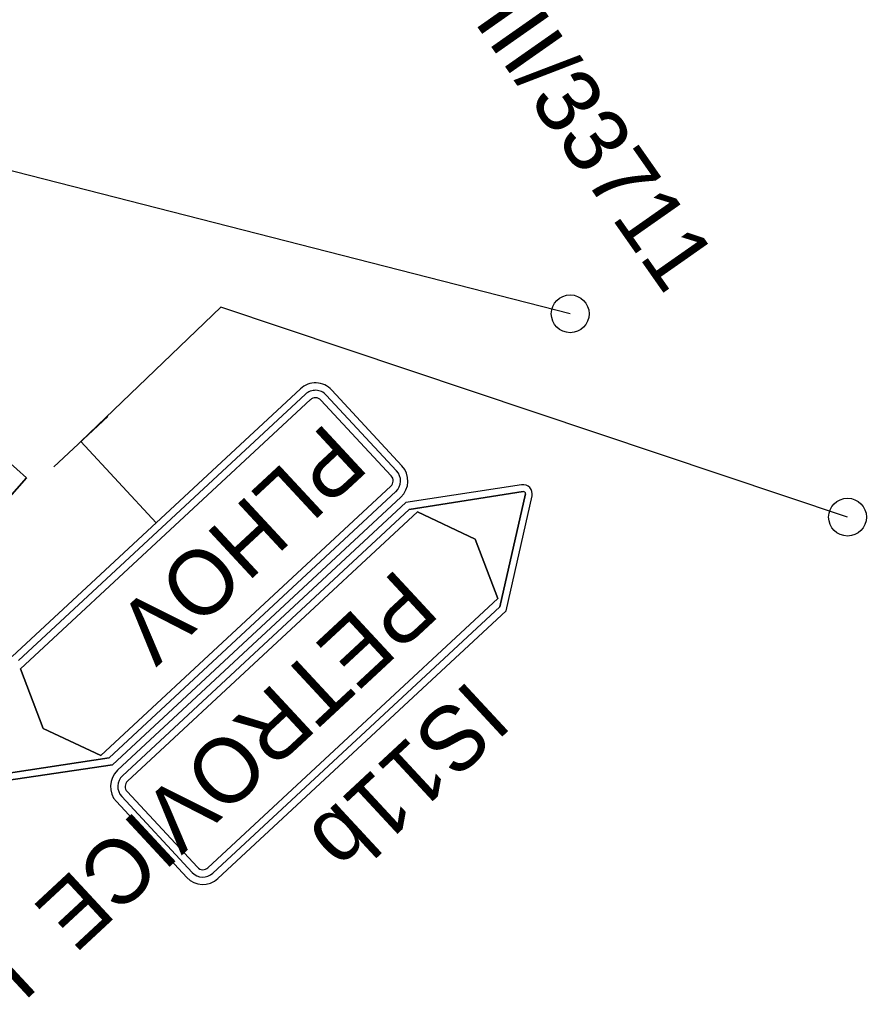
# Model space of a CAD drawing. Extents: x -688893 to -679983, y -1088371 to -1075771.
# Drawn here: x -684623 to -683934, y -1077302 to -1076507 of the extents above; entities that cross this region are included whole.
import ezdxf

# ---------------------------------------------------------------- set-up
doc = ezdxf.new("R2010")
doc.units = 0
for name, color, linetype in [('S popis', 7, 'Continuous'), ('SDZ', 7, 'Continuous'), ('SDZ ozn', 7, 'Continuous'), ('SDZ plochy', 7, 'Continuous'), ('SDZ symbol', 7, 'Continuous')]:
    doc.layers.add(name, color=color, linetype=linetype)

msp = doc.modelspace()

# ---------------------------------------------------------------- linework, layer by layer
at = {"layer": 'SDZ'}
for p, q in [((-684954.23, -1076581.35), (-684617.13, -1076879.46)), ((-684628.89, -1077024.86), (-684394.53, -1076807.26)), ((-684390.45, -1076811.66), (-684623.49, -1077028.03)), ((-684316.34, -1076873.84), (-684373.49, -1076812.28)), ((-684369.09, -1076808.2), (-684311.94, -1076869.76)), ((-684622.04, -1077034.88), (-684386.37, -1076816.05)), ((-684377.89, -1076816.37), (-684320.73, -1076877.92)), ((-684550.96, -1076829.69), (-684594.93, -1076870.52)), ((-684511.71, -1076916.06), (-684572.95, -1076850.11)), ((-684617.13, -1076879.46), (-684815.87, -1077104.19)), ((-684214.7, -1076885.22), (-684308.8, -1076899.59)), ((-684321.05, -1076886.4), (-684556.72, -1077105.23)), ((-684550, -1077107.18), (-684316.96, -1076890.8)), ((-684306.04, -1076905.22), (-684213.35, -1076890.73)), ((-684211.65, -1076892.55), (-684232.55, -1076984.36)), ((-684312.88, -1076895.2), (-684547.24, -1077112.8)), ((-684308.8, -1076899.59), (-684543.15, -1077117.19)), ((-684227.15, -1076987.53), (-684206.25, -1076894.27)), ((-684206.29, -1076894.48), (-684206.29, -1076894.48)), ((-684539.07, -1077121.59), (-684306.04, -1076905.22)), ((-684299.31, -1076907.16), (-684534.99, -1077125.99)), ((-684252.58, -1076929.27), (-684299.31, -1076907.16)), ((-684233.99, -1076977.51), (-684252.58, -1076929.27)), ((-684469.67, -1077196.34), (-684233.99, -1076977.51)), ((-684232.55, -1076984.36), (-684465.58, -1077200.74)), ((-684461.5, -1077205.13), (-684227.15, -1076987.53)), ((-684603.45, -1077083.12), (-684622.04, -1077034.88)), ((-684556.72, -1077105.23), (-684603.45, -1077083.12)), ((-684643.11, -1077121.22), (-684550, -1077107.18)), ((-684547.24, -1077112.8), (-684641.79, -1077126.74)), ((-684482.54, -1077200.11), (-684539.7, -1077138.55)), ((-684535.3, -1077134.47), (-684478.15, -1077196.02)), ((-684544.1, -1077142.63), (-684486.94, -1077204.19))]:
    msp.add_line(p, q, dxfattribs=at)
for points in [[(-684175.23, -1076746.27), (-685042.81, -1076524.62), (-685121.02, -1076634.1)], [(-683949.83, -1076911.5), (-684459.24, -1076740.97), (-684572.95, -1076850.11)]]:
    msp.add_lwpolyline(points, dxfattribs=at)
for centre in [(-684175.23, -1076746.27), (-683949.83, -1076911.5)]:
    msp.add_circle(centre, 15.36, dxfattribs=at)
for centre, radius, start, end in [((-684382.28, -1076820.45), 18, 42.87701, 132.87701), ((-684382.28, -1076820.45), 12, 42.87701, 132.87701), ((-684382.28, -1076820.45), 6, 42.87701, 132.87701), ((-684325.13, -1076882.01), 12, 312.87701, 42.87701), ((-684325.13, -1076882.01), 18, 312.87701, 42.87701), ((-684325.13, -1076882.01), 6, 312.87701, 42.87701), ((-684213.56, -1076892.63), 7.5, 347.36697, 98.68524), ((-684213.11, -1076892.22), 1.5, 347.17767, 98.88055), ((-684530.91, -1077130.39), 18, 132.87701, 222.87701), ((-684530.91, -1077130.39), 12, 132.87701, 222.87701), ((-684530.91, -1077130.39), 6, 132.87701, 222.87701), ((-684473.75, -1077191.94), 12, 222.87701, 312.87701), ((-684473.75, -1077191.94), 6, 222.87701, 312.87701), ((-684473.75, -1077191.94), 18, 222.87701, 312.87701)]:
    msp.add_arc(centre, radius, start, end, dxfattribs=at)
at = {"layer": 'SDZ plochy'}
for p, q in [((-684617.13, -1076879.46), (-684954.23, -1076581.35)), ((-684394.53, -1076807.26), (-684628.89, -1077024.86)), ((-684623.49, -1077028.03), (-684390.45, -1076811.66)), ((-684390.45, -1076811.66), (-684623.49, -1077028.03)), ((-684373.49, -1076812.28), (-684316.34, -1076873.84)), ((-684316.34, -1076873.84), (-684373.49, -1076812.28)), ((-684311.94, -1076869.76), (-684369.09, -1076808.2)), ((-684386.37, -1076816.05), (-684622.04, -1077034.88)), ((-684622.04, -1077034.88), (-684386.37, -1076816.05)), ((-684320.73, -1076877.92), (-684377.89, -1076816.37)), ((-684377.89, -1076816.37), (-684320.73, -1076877.92)), ((-684815.87, -1077104.19), (-684617.13, -1076879.46)), ((-684214.7, -1076885.22), (-684308.8, -1076899.59)), ((-684556.72, -1077105.23), (-684321.05, -1076886.4)), ((-684321.05, -1076886.4), (-684556.72, -1077105.23)), ((-684316.96, -1076890.8), (-684550, -1077107.18)), ((-684550, -1077107.18), (-684316.96, -1076890.8)), ((-684306.04, -1076905.22), (-684213.35, -1076890.73)), ((-684213.35, -1076890.73), (-684306.04, -1076905.22)), ((-684211.65, -1076892.55), (-684232.55, -1076984.36)), ((-684232.55, -1076984.36), (-684211.65, -1076892.55)), ((-684547.24, -1077112.8), (-684312.88, -1076895.2)), ((-684308.8, -1076899.59), (-684543.15, -1077117.19)), ((-684227.15, -1076987.53), (-684206.25, -1076894.27)), ((-684539.07, -1077121.59), (-684306.04, -1076905.22)), ((-684306.04, -1076905.22), (-684539.07, -1077121.59)), ((-684299.31, -1076907.16), (-684534.99, -1077125.99)), ((-684534.99, -1077125.99), (-684299.31, -1076907.16)), ((-684252.58, -1076929.27), (-684299.31, -1076907.16)), ((-684299.31, -1076907.16), (-684252.58, -1076929.27)), ((-684233.99, -1076977.51), (-684252.58, -1076929.27)), ((-684252.58, -1076929.27), (-684233.99, -1076977.51)), ((-684469.67, -1077196.34), (-684233.99, -1076977.51)), ((-684233.99, -1076977.51), (-684469.67, -1077196.34)), ((-684232.55, -1076984.36), (-684465.58, -1077200.74)), ((-684465.58, -1077200.74), (-684232.55, -1076984.36)), ((-684461.5, -1077205.13), (-684227.15, -1076987.53)), ((-684622.04, -1077034.88), (-684603.45, -1077083.12)), ((-684603.45, -1077083.12), (-684622.04, -1077034.88)), ((-684603.45, -1077083.12), (-684556.72, -1077105.23)), ((-684556.72, -1077105.23), (-684603.45, -1077083.12)), ((-684550, -1077107.18), (-684643.11, -1077121.22)), ((-684643.11, -1077121.22), (-684550, -1077107.18)), ((-684641.79, -1077126.74), (-684547.24, -1077112.8)), ((-684482.54, -1077200.11), (-684539.7, -1077138.55)), ((-684539.7, -1077138.55), (-684482.54, -1077200.11)), ((-684535.3, -1077134.47), (-684478.15, -1077196.02)), ((-684478.15, -1077196.02), (-684535.3, -1077134.47)), ((-684544.1, -1077142.63), (-684486.94, -1077204.19))]:
    msp.add_line(p, q, dxfattribs=at)
for centre, radius, start, end in [((-684382.28, -1076820.45), 18, 42.87701, 132.87701), ((-684382.28, -1076820.45), 12, 42.87701, 132.87701), ((-684382.28, -1076820.45), 12, 42.87701, 132.87701), ((-684382.28, -1076820.45), 6, 42.87701, 132.87701), ((-684382.28, -1076820.45), 6, 42.87701, 132.87701), ((-684325.13, -1076882.01), 12, 312.87701, 42.87701), ((-684325.13, -1076882.01), 12, 312.87701, 42.87701), ((-684325.13, -1076882.01), 18, 312.87701, 42.87701), ((-684325.13, -1076882.01), 6, 312.87701, 42.87701), ((-684325.13, -1076882.01), 6, 312.87701, 42.87701), ((-684213.56, -1076892.63), 7.5, 347.36697, 98.68524), ((-684213.11, -1076892.22), 1.5, 347.17767, 98.88055), ((-684213.11, -1076892.22), 1.5, 347.17767, 98.88055), ((-684530.91, -1077130.39), 18, 132.87701, 222.87701), ((-684530.91, -1077130.39), 12, 132.87701, 222.87701), ((-684530.91, -1077130.39), 12, 132.87701, 222.87701), ((-684530.91, -1077130.39), 6, 132.87701, 222.87701), ((-684530.91, -1077130.39), 6, 132.87701, 222.87701), ((-684473.75, -1077191.94), 12, 222.87701, 312.87701), ((-684473.75, -1077191.94), 12, 222.87701, 312.87701), ((-684473.75, -1077191.94), 6, 222.87701, 312.87701), ((-684473.75, -1077191.94), 6, 222.87701, 312.87701), ((-684473.75, -1077191.94), 18, 222.87701, 312.87701)]:
    msp.add_arc(centre, radius, start, end, dxfattribs=at)

# ---------------------------------------------------------------- texts
at = {"layer": 'S popis'}
msp.add_text('silnice III/33711', height=52.5, rotation=305.01854, dxfattribs=at).set_placement((-684377.43, -1076332.43))
at = {"layer": 'SDZ ozn'}
msp.add_text('IS11b', height=52.5, rotation=222.87701, dxfattribs=at).set_placement((-684256.62, -1077042.45))
at = {"layer": 'SDZ symbol'}
for s, p in [('PLHOV', (-684373.19, -1076833.5)), ('PETROVICE  I', (-684315.44, -1076951.82))]:
    msp.add_text(s, height=52.5, rotation=222.87701, dxfattribs=at).set_placement(p)

doc.saveas('drawing.dxf')
